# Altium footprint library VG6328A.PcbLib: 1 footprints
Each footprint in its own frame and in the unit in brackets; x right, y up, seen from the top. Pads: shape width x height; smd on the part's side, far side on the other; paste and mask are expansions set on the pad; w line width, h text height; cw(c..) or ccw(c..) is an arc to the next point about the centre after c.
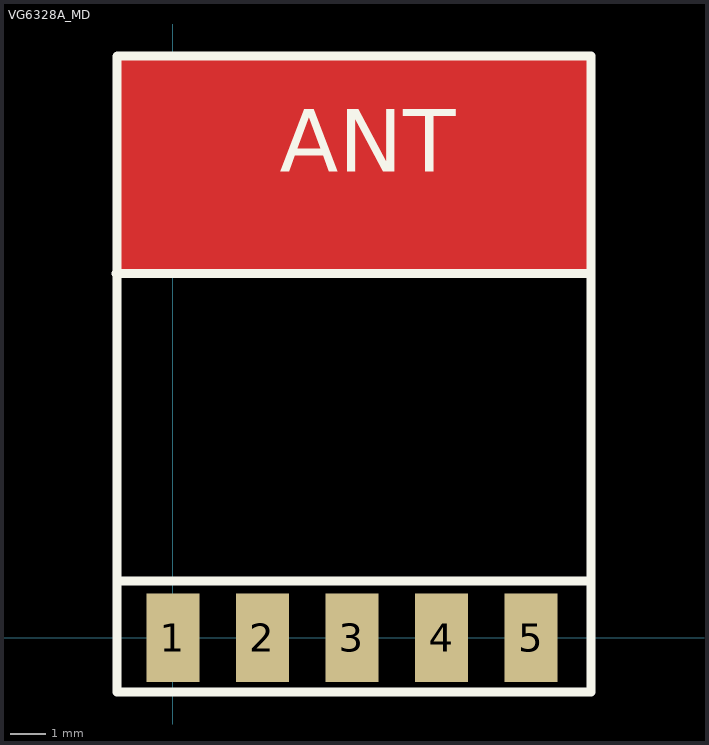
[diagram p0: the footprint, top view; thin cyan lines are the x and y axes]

## VG6328A_MD [mm]
pads (5):
  rect 1.5x2.5 smd: 1(0,0) 2(2.54,0) 3(5.08,0) 4(7.62,0) 5(10.16,0)
Top Layer:
  pour cut-out: -1.575,16.498 11.862,16.502 11.862,10.328 -1.575,10.328
Bottom Layer:
  pour cut-out: -1.6,16.498 11.887,16.502 11.887,10.328 -1.6,10.328
Top Overlay:
  lines w0.254: -1.613,10.323 11.786,10.323 ; -1.501,1.61 11.794,1.61 ; -1.589,-1.545 11.862,-1.545 11.862,16.5 -1.575,16.5 -1.589,16.486 -1.589,-1.545
  text "ANT" at 3.036,12.633 h3.05
Keep-Out Layer:
  lines w0.152: -1.575,0.5 -1.575,16.5 11.862,16.5 11.862,0.5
